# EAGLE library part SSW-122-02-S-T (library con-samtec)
THROUGH-HOLE .025" SQ POST SOCKET Source: Samtec SSW.pdf
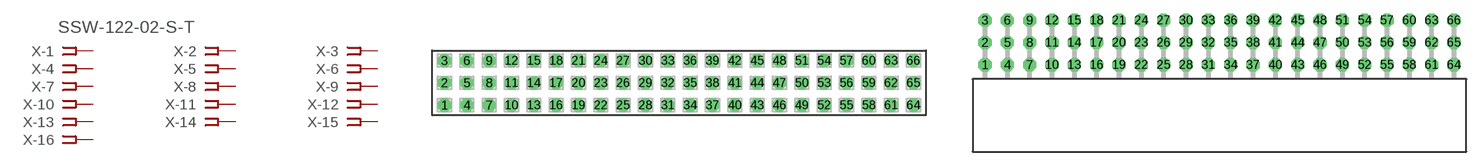
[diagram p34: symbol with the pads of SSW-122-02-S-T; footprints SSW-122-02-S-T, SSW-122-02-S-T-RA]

Designator prefix X; gates -1=FPINV -2=FPIN -3=FPIN -4=FPIN -5=FPIN -6=FPIN -7=FPIN -8=FPIN -9=FPIN -10=FPIN -11=FPIN -12=FPIN -13=FPIN -14=FPIN -15=FPIN -16=FPIN -17=FPIN -18=FPIN -19=FPIN -20=FPIN -21=FPIN -22=FPIN -23=FPIN -24=FPIN -25=FPIN -26=FPIN -27=FPIN -28=FPIN -29=FPIN -30=FPIN -31=FPIN -32=FPIN -33=FPIN -34=FPIN -35=FPIN -36=FPIN -37=FPIN -38=FPIN -39=FPIN -40=FPIN -41=FPIN -42=FPIN -43=FPIN -44=FPIN -45=FPIN -46=FPIN -47=FPIN -48=FPIN -49=FPIN -50=FPIN -51=FPIN -52=FPIN -53=FPIN -54=FPIN -55=FPIN -56=FPIN -57=FPIN -58=FPIN -59=FPIN -60=FPIN -61=FPIN -62=FPIN -63=FPIN -64=FPIN -65=FPIN -66=FPIN

## SSW-122-02-S-T (MPN: SSW-122-02-S-T; OC_FARNELL: unknown; OC_NEWARK: 82P8754)  [SSW-122-02-S-T]
1  -1:1  pas
2  -2:1  pas
3  -3:1  pas
4  -4:1  pas
5  -5:1  pas
6  -6:1  pas
7  -7:1  pas
8  -8:1  pas
9  -9:1  pas
10  -10:1  pas
11  -11:1  pas
12  -12:1  pas
13  -13:1  pas
14  -14:1  pas
15  -15:1  pas
16  -16:1  pas
17  -17:1  pas
18  -18:1  pas
19  -19:1  pas
20  -20:1  pas
21  -21:1  pas
22  -22:1  pas
23  -23:1  pas
24  -24:1  pas
25  -25:1  pas
26  -26:1  pas
27  -27:1  pas
28  -28:1  pas
29  -29:1  pas
30  -30:1  pas
31  -31:1  pas
32  -32:1  pas
33  -33:1  pas
34  -34:1  pas
35  -35:1  pas
36  -36:1  pas
37  -37:1  pas
38  -38:1  pas
39  -39:1  pas
40  -40:1  pas
41  -41:1  pas
42  -42:1  pas
43  -43:1  pas
44  -44:1  pas
45  -45:1  pas
46  -46:1  pas
47  -47:1  pas
48  -48:1  pas
49  -49:1  pas
50  -50:1  pas
51  -51:1  pas
52  -52:1  pas
53  -53:1  pas
54  -54:1  pas
55  -55:1  pas
56  -56:1  pas
57  -57:1  pas
58  -58:1  pas
59  -59:1  pas
60  -60:1  pas
61  -61:1  pas
62  -62:1  pas
63  -63:1  pas
64  -64:1  pas
65  -65:1  pas
66  -66:1  pas

## SSW-122-02-S-TRA (OC_FARNELL: unknown; OC_NEWARK: unknown)  [SSW-122-02-S-T-RA]
Pads as for SSW-122-02-S-T

## Footprint SSW-122-02-S-T (pad centres in mm)
THROUGH-HOLE .025" SQ POST SOCKET Source: Samtec SSW.pdf
drill 1 pad 1.5 octagon: 1 -26.67,-2.54; 2 -26.67,0; 3 -26.67,2.54; 4 -24.13,-2.54; 5 -24.13,0; 6 -24.13,2.54; 7 -21.59,-2.54; 8 -21.59,0; 9 -21.59,2.54; 10 -19.05,-2.54; 11 -19.05,0; 12 -19.05,2.54; 13 -16.51,-2.54; 14 -16.51,0; 15 -16.51,2.54; 16 -13.97,-2.54; 17 -13.97,0; 18 -13.97,2.54; 19 -11.43,-2.54; 20 -11.43,0; 21 -11.43,2.54; 22 -8.89,-2.54; 23 -8.89,0; 24 -8.89,2.54; 25 -6.35,-2.54; 26 -6.35,0; 27 -6.35,2.54; 28 -3.81,-2.54; 29 -3.81,0; 30 -3.81,2.54; 31 -1.27,-2.54; 32 -1.27,0; 33 -1.27,2.54; 34 1.27,-2.54; 35 1.27,0; 36 1.27,2.54; 37 3.81,-2.54; 38 3.81,0; 39 3.81,2.54; 40 6.35,-2.54; 41 6.35,0; 42 6.35,2.54; 43 8.89,-2.54; 44 8.89,0; 45 8.89,2.54; 46 11.43,-2.54; 47 11.43,0; 48 11.43,2.54; 49 13.97,-2.54; 50 13.97,0; 51 13.97,2.54; 52 16.51,-2.54; 53 16.51,0; 54 16.51,2.54; 55 19.05,-2.54; 56 19.05,0; 57 19.05,2.54; 58 21.59,-2.54; 59 21.59,0; 60 21.59,2.54; 61 24.13,-2.54; 62 24.13,0; 63 24.13,2.54; 64 26.67,-2.54; 65 26.67,0; 66 26.67,2.54

## Footprint SSW-122-02-S-T-RA (pad centres in mm)
THROUGH-HOLE .025" SQ POST SOCKET Source: Samtec SSW.pdf
drill 1 pad 1.5 octagon: 1 -26.67,1.524; 2 -26.67,4.064; 3 -26.67,6.604; 4 -24.13,1.524; 5 -24.13,4.064; 6 -24.13,6.604; 7 -21.59,1.524; 8 -21.59,4.064; 9 -21.59,6.604; 10 -19.05,1.524; 11 -19.05,4.064; 12 -19.05,6.604; 13 -16.51,1.524; 14 -16.51,4.064; 15 -16.51,6.604; 16 -13.97,1.524; 17 -13.97,4.064; 18 -13.97,6.604; 19 -11.43,1.524; 20 -11.43,4.064; 21 -11.43,6.604; 22 -8.89,1.524; 23 -8.89,4.064; 24 -8.89,6.604; 25 -6.35,1.524; 26 -6.35,4.064; 27 -6.35,6.604; 28 -3.81,1.524; 29 -3.81,4.064; 30 -3.81,6.604; 31 -1.27,1.524; 32 -1.27,4.064; 33 -1.27,6.604; 34 1.27,1.524; 35 1.27,4.064; 36 1.27,6.604; 37 3.81,1.524; 38 3.81,4.064; 39 3.81,6.604; 40 6.35,1.524; 41 6.35,4.064; 42 6.35,6.604; 43 8.89,1.524; 44 8.89,4.064; 45 8.89,6.604; 46 11.43,1.524; 47 11.43,4.064; 48 11.43,6.604; 49 13.97,1.524; 50 13.97,4.064; 51 13.97,6.604; 52 16.51,1.524; 53 16.51,4.064; 54 16.51,6.604; 55 19.05,1.524; 56 19.05,4.064; 57 19.05,6.604; 58 21.59,1.524; 59 21.59,4.064; 60 21.59,6.604; 61 24.13,1.524; 62 24.13,4.064; 63 24.13,6.604; 64 26.67,1.524; 65 26.67,4.064; 66 26.67,6.604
